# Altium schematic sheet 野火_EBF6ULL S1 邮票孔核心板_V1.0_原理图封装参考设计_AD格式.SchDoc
size 431 x 279 mm
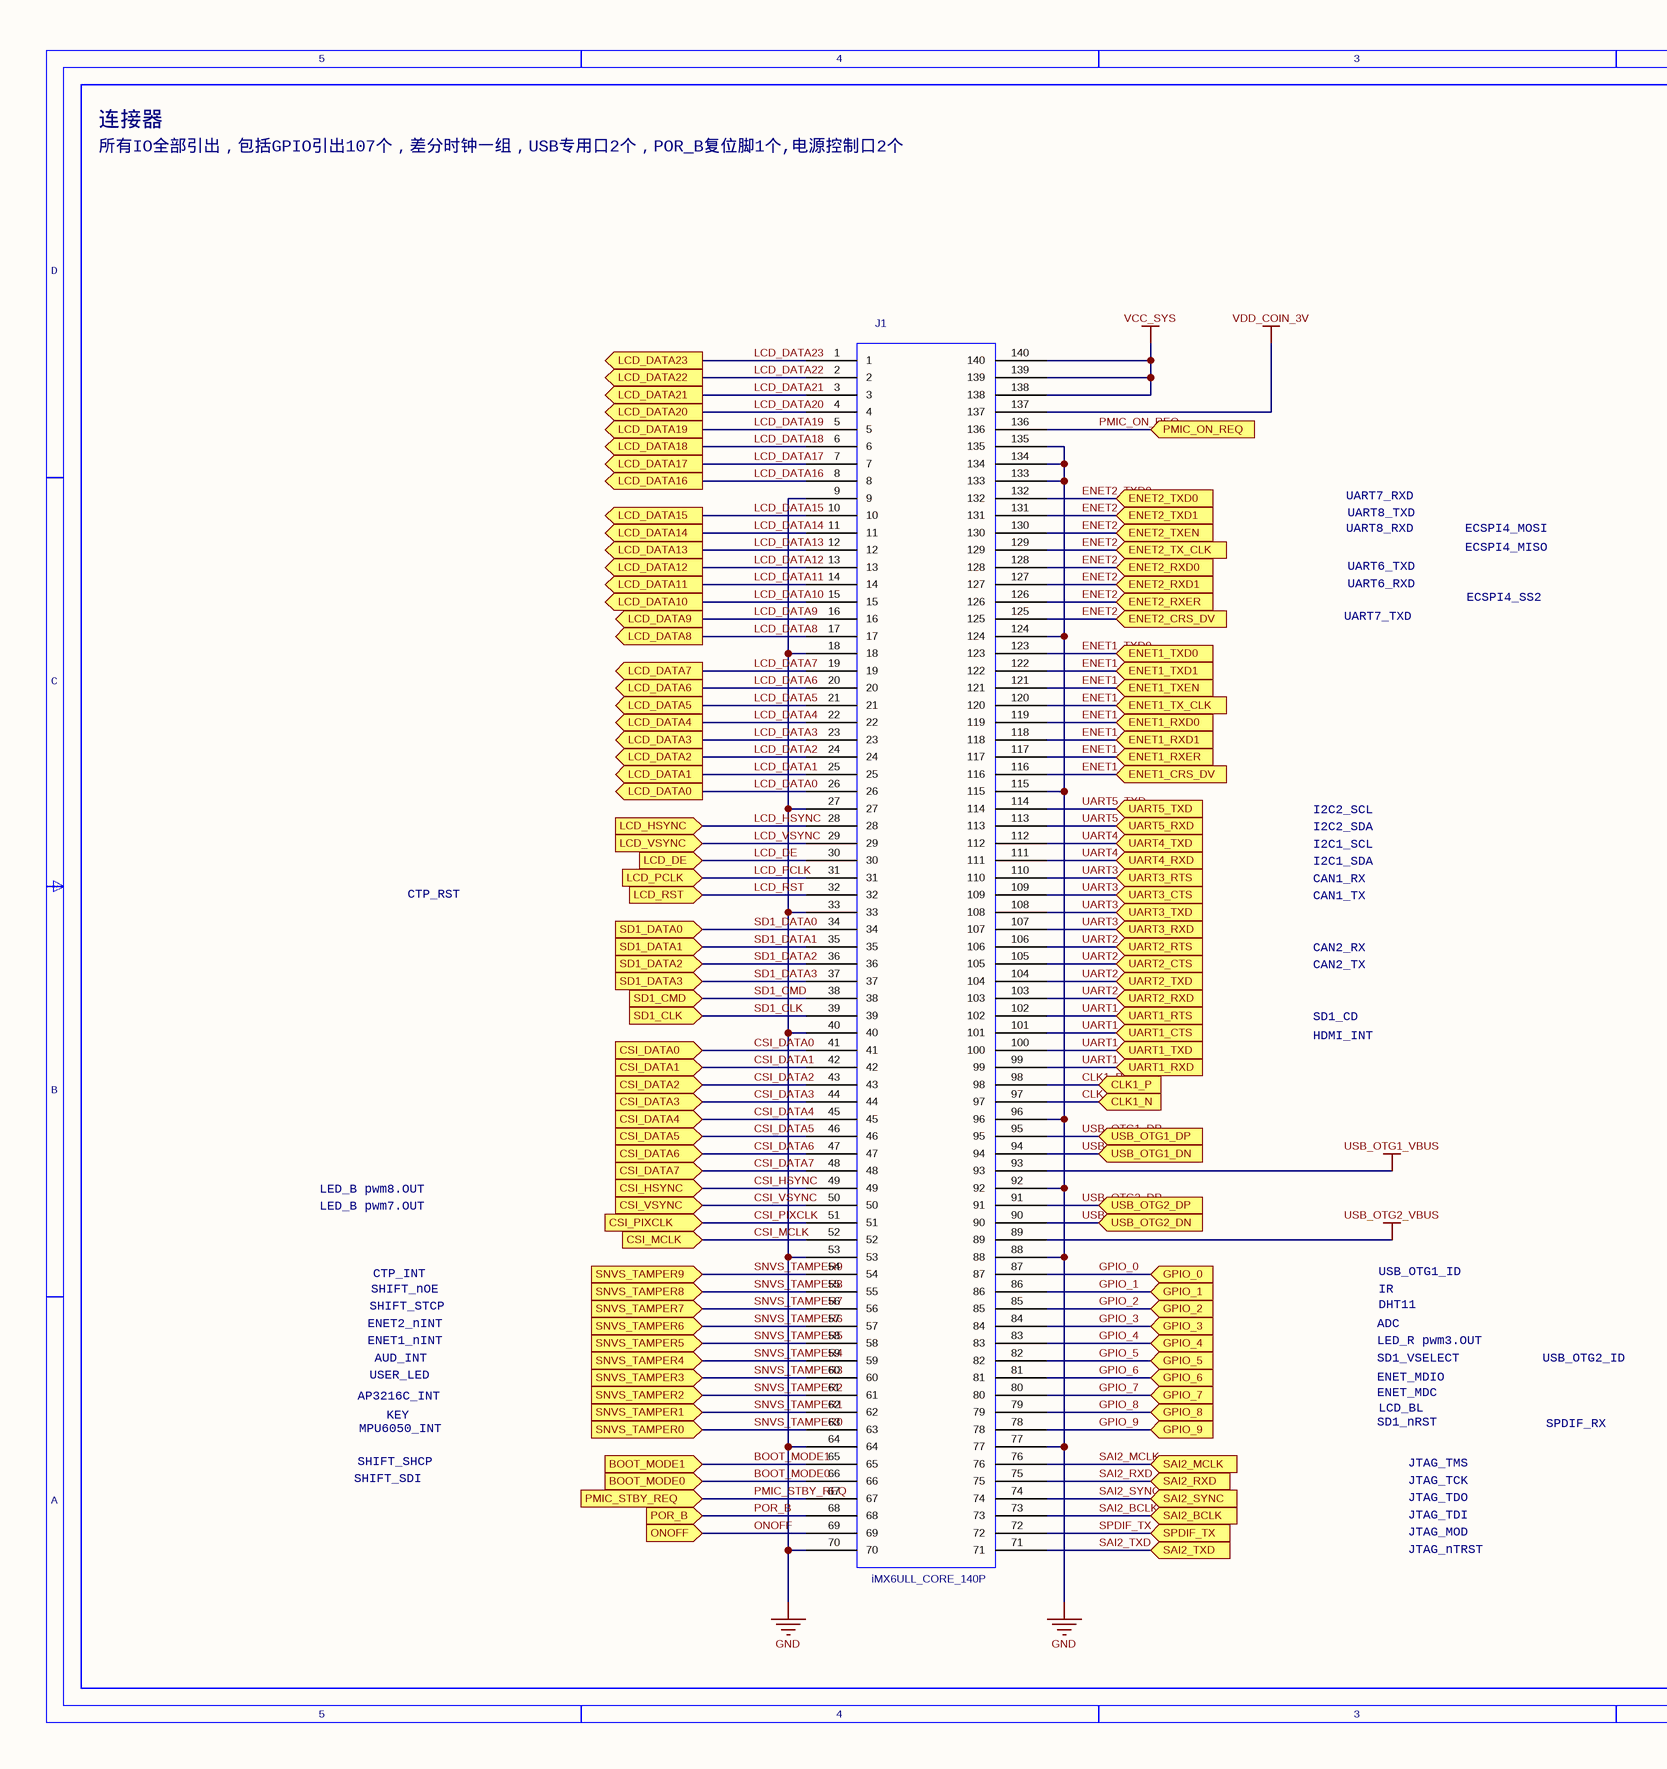
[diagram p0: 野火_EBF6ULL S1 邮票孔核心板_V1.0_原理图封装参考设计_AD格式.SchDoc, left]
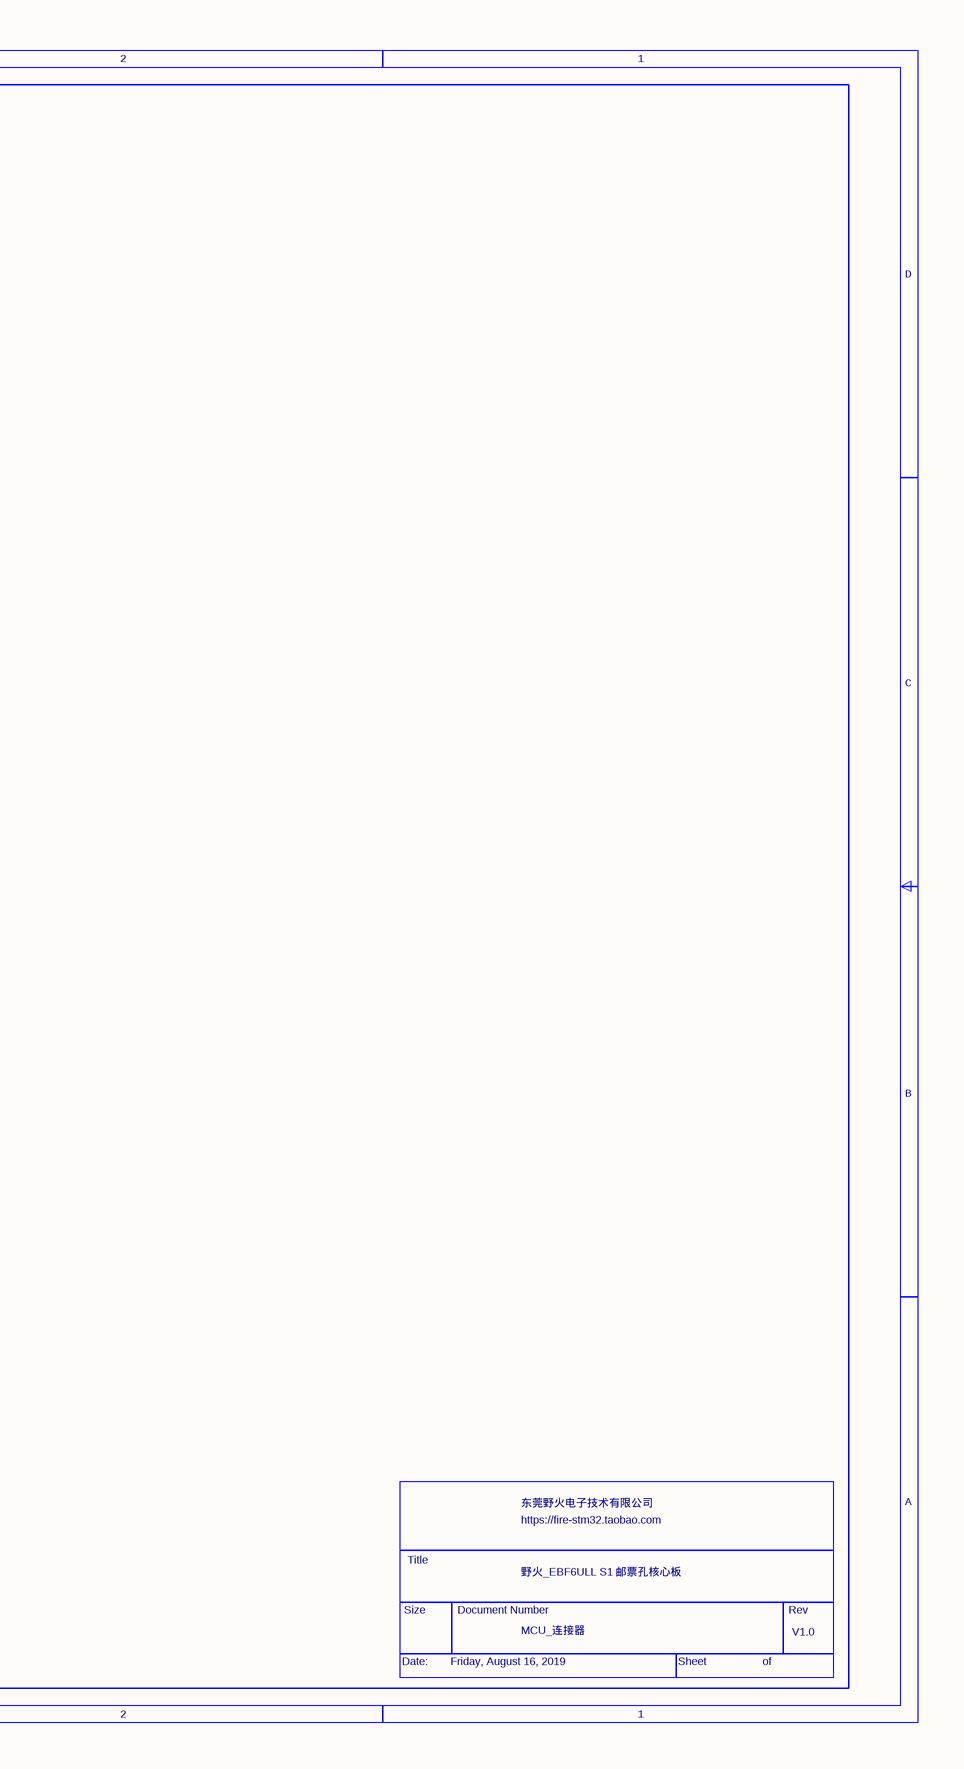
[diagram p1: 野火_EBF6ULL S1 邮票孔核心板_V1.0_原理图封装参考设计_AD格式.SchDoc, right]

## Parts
J1  IMX6ULL_CORE_140P  [6ULL_CORE_140P_39X39]

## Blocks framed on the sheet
连接器: J1

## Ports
BOOT_MODE0, BOOT_MODE1, CLK1_N (in), CLK1_P (in), CSI_DATA0, CSI_DATA1, CSI_DATA2, CSI_DATA3, CSI_DATA4, CSI_DATA5, CSI_DATA6, CSI_DATA7, CSI_HSYNC, CSI_MCLK, CSI_PIXCLK, CSI_VSYNC, ENET1_CRS_DV (in), ENET1_RXD0 (in), ENET1_RXD1 (in), ENET1_RXER (in), ENET1_TX_CLK (in), ENET1_TXD0 (in), ENET1_TXD1 (in), ENET1_TXEN (in), ENET2_CRS_DV (in), ENET2_RXD0 (in), ENET2_RXD1 (in), ENET2_RXER (in), ENET2_TX_CLK (in), ENET2_TXD0 (in), ENET2_TXD1 (in), ENET2_TXEN (in), GPIO_0 (in), GPIO_1 (in), GPIO_2 (in), GPIO_3 (in), GPIO_4 (in), GPIO_5 (in), GPIO_6 (in), GPIO_7 (in), GPIO_8 (in), GPIO_9 (in), LCD_DATA0 (out), LCD_DATA1 (out), LCD_DATA2 (out), LCD_DATA3 (out), LCD_DATA4 (out), LCD_DATA5 (out), LCD_DATA6 (out), LCD_DATA7 (out), LCD_DATA8 (out), LCD_DATA9 (out), LCD_DATA10 (out), LCD_DATA11 (out), LCD_DATA12 (out), LCD_DATA13 (out), LCD_DATA14 (out), LCD_DATA15 (out), LCD_DATA16 (out), LCD_DATA17 (out), LCD_DATA18 (out), LCD_DATA19 (out), LCD_DATA20 (out), LCD_DATA21 (out), LCD_DATA22 (out), LCD_DATA23 (out), LCD_DE, LCD_HSYNC, LCD_PCLK, LCD_RST, LCD_VSYNC, ONOFF, PMIC_ON_REQ, PMIC_STBY_REQ, POR_B, SAI2_BCLK (in), SAI2_MCLK (in), SAI2_RXD (in), SAI2_SYNC (in), SAI2_TXD (in), SD1_CLK, SD1_CMD, SD1_DATA0, SD1_DATA1, SD1_DATA2, SD1_DATA3, SNVS_TAMPER0, SNVS_TAMPER1, SNVS_TAMPER2, SNVS_TAMPER3, SNVS_TAMPER4, SNVS_TAMPER5, SNVS_TAMPER6, SNVS_TAMPER7, SNVS_TAMPER8, SNVS_TAMPER9, SPDIF_TX (in), UART1_CTS, UART1_RTS, UART1_RXD, UART1_TXD, UART2_CTS, UART2_RTS, UART2_RXD, UART2_TXD, UART3_CTS, UART3_RTS, UART3_RXD, UART3_TXD, UART4_RXD, UART4_TXD, UART5_RXD, UART5_TXD, USB_OTG1_DN (in), USB_OTG1_DP (in), USB_OTG2_DN (in), USB_OTG2_DP (in)

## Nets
GND: J1.9 J1.18 J1.27 J1.33 J1.40 J1.53 J1.64 J1.70 J1.77 J1.88 J1.92 J1.96 J1.115 J1.124 J1.133 J1.134 J1.135
USB_OTG1_VBUS: J1.93
USB_OTG2_VBUS: J1.89
VCC_SYS: J1.138 J1.139 J1.140
VDD_COIN_3V: J1.137
BOOT_MODE0: J1.66 ; port BOOT_MODE0
BOOT_MODE1: J1.65 ; port BOOT_MODE1
CLK1_N: J1.97 ; port CLK1_N
CLK1_P: J1.98 ; port CLK1_P
CSI_DATA0: J1.41 ; port CSI_DATA0
CSI_DATA1: J1.42 ; port CSI_DATA1
CSI_DATA2: J1.43 ; port CSI_DATA2
CSI_DATA3: J1.44 ; port CSI_DATA3
CSI_DATA4: J1.45 ; port CSI_DATA4
CSI_DATA5: J1.46 ; port CSI_DATA5
CSI_DATA6: J1.47 ; port CSI_DATA6
CSI_DATA7: J1.48 ; port CSI_DATA7
CSI_HSYNC: J1.49 ; port CSI_HSYNC
CSI_MCLK: J1.52 ; port CSI_MCLK
CSI_PIXCLK: J1.51 ; port CSI_PIXCLK
CSI_VSYNC: J1.50 ; port CSI_VSYNC
ENET1_CRS_DV: J1.116 ; port ENET1_CRS_DV
ENET1_RXD0: J1.119 ; port ENET1_RXD0
ENET1_RXD1: J1.118 ; port ENET1_RXD1
ENET1_RXER: J1.117 ; port ENET1_RXER
ENET1_TX_CLK: J1.120 ; port ENET1_TX_CLK
ENET1_TXD0: J1.123 ; port ENET1_TXD0
ENET1_TXD1: J1.122 ; port ENET1_TXD1
ENET1_TXEN: J1.121 ; port ENET1_TXEN
ENET2_CRS_DV: J1.125 ; port ENET2_CRS_DV
ENET2_RXD0: J1.128 ; port ENET2_RXD0
ENET2_RXD1: J1.127 ; port ENET2_RXD1
ENET2_RXER: J1.126 ; port ENET2_RXER
ENET2_TX_CLK: J1.129 ; port ENET2_TX_CLK
ENET2_TXD0: J1.132 ; port ENET2_TXD0
ENET2_TXD1: J1.131 ; port ENET2_TXD1
ENET2_TXEN: J1.130 ; port ENET2_TXEN
GPIO_0: J1.87 ; port GPIO_0
GPIO_1: J1.86 ; port GPIO_1
GPIO_2: J1.85 ; port GPIO_2
GPIO_3: J1.84 ; port GPIO_3
GPIO_4: J1.83 ; port GPIO_4
GPIO_5: J1.82 ; port GPIO_5
GPIO_6: J1.81 ; port GPIO_6
GPIO_7: J1.80 ; port GPIO_7
GPIO_8: J1.79 ; port GPIO_8
GPIO_9: J1.78 ; port GPIO_9
LCD_DATA0: J1.26 ; port LCD_DATA0
LCD_DATA1: J1.25 ; port LCD_DATA1
LCD_DATA2: J1.24 ; port LCD_DATA2
LCD_DATA3: J1.23 ; port LCD_DATA3
LCD_DATA4: J1.22 ; port LCD_DATA4
LCD_DATA5: J1.21 ; port LCD_DATA5
LCD_DATA6: J1.20 ; port LCD_DATA6
LCD_DATA7: J1.19 ; port LCD_DATA7
LCD_DATA8: J1.17 ; port LCD_DATA8
LCD_DATA9: J1.16 ; port LCD_DATA9
LCD_DATA10: J1.15 ; port LCD_DATA10
LCD_DATA11: J1.14 ; port LCD_DATA11
LCD_DATA12: J1.13 ; port LCD_DATA12
LCD_DATA13: J1.12 ; port LCD_DATA13
LCD_DATA14: J1.11 ; port LCD_DATA14
LCD_DATA15: J1.10 ; port LCD_DATA15
LCD_DATA16: J1.8 ; port LCD_DATA16
LCD_DATA17: J1.7 ; port LCD_DATA17
LCD_DATA18: J1.6 ; port LCD_DATA18
LCD_DATA19: J1.5 ; port LCD_DATA19
LCD_DATA20: J1.4 ; port LCD_DATA20
LCD_DATA21: J1.3 ; port LCD_DATA21
LCD_DATA22: J1.2 ; port LCD_DATA22
LCD_DATA23: J1.1 ; port LCD_DATA23
LCD_DE: J1.30 ; port LCD_DE
LCD_HSYNC: J1.28 ; port LCD_HSYNC
LCD_PCLK: J1.31 ; port LCD_PCLK
LCD_RST: J1.32 ; port LCD_RST
LCD_VSYNC: J1.29 ; port LCD_VSYNC
ONOFF: J1.69 ; port ONOFF
PMIC_ON_REQ: J1.136 ; port PMIC_ON_REQ
PMIC_STBY_REQ: J1.67 ; port PMIC_STBY_REQ
POR_B: J1.68 ; port POR_B
SAI2_BCLK: J1.73 ; port SAI2_BCLK
SAI2_MCLK: J1.76 ; port SAI2_MCLK
SAI2_RXD: J1.75 ; port SAI2_RXD
SAI2_SYNC: J1.74 ; port SAI2_SYNC
SAI2_TXD: J1.71 ; port SAI2_TXD
SD1_CLK: J1.39 ; port SD1_CLK
SD1_CMD: J1.38 ; port SD1_CMD
SD1_DATA0: J1.34 ; port SD1_DATA0
SD1_DATA1: J1.35 ; port SD1_DATA1
SD1_DATA2: J1.36 ; port SD1_DATA2
SD1_DATA3: J1.37 ; port SD1_DATA3
SNVS_TAMPER0: J1.63 ; port SNVS_TAMPER0
SNVS_TAMPER1: J1.62 ; port SNVS_TAMPER1
SNVS_TAMPER2: J1.61 ; port SNVS_TAMPER2
SNVS_TAMPER3: J1.60 ; port SNVS_TAMPER3
SNVS_TAMPER4: J1.59 ; port SNVS_TAMPER4
SNVS_TAMPER5: J1.58 ; port SNVS_TAMPER5
SNVS_TAMPER6: J1.57 ; port SNVS_TAMPER6
SNVS_TAMPER7: J1.56 ; port SNVS_TAMPER7
SNVS_TAMPER8: J1.55 ; port SNVS_TAMPER8
SNVS_TAMPER9: J1.54 ; port SNVS_TAMPER9
SPDIF_TX: J1.72 ; port SPDIF_TX
UART1_CTS: J1.101 ; port UART1_CTS
UART1_RTS: J1.102 ; port UART1_RTS
UART1_RXD: J1.99 ; port UART1_RXD
UART1_TXD: J1.100 ; port UART1_TXD
UART2_CTS: J1.105 ; port UART2_CTS
UART2_RTS: J1.106 ; port UART2_RTS
UART2_RXD: J1.103 ; port UART2_RXD
UART2_TXD: J1.104 ; port UART2_TXD
UART3_CTS: J1.109 ; port UART3_CTS
UART3_RTS: J1.110 ; port UART3_RTS
UART3_RXD: J1.107 ; port UART3_RXD
UART3_TXD: J1.108 ; port UART3_TXD
UART4_RXD: J1.111 ; port UART4_RXD
UART4_TXD: J1.112 ; port UART4_TXD
UART5_RXD: J1.113 ; port UART5_RXD
UART5_TXD: J1.114 ; port UART5_TXD
USB_OTG1_DN: J1.94 ; port USB_OTG1_DN
USB_OTG1_DP: J1.95 ; port USB_OTG1_DP
USB_OTG2_DN: J1.90 ; port USB_OTG2_DN
USB_OTG2_DP: J1.91 ; port USB_OTG2_DP

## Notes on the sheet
- 5
- 4
- 3
- 2
- 1
- 所有IO全部引出，包括GPIO引出107个，差分时钟一组，USB专用口2个，POR_B复位脚1个,电源控制口2个
- D
- UART7_RXD
- UART8_RXD
- UART6_TXD
- UART6_RXD
- UART8_TXD
- ECSPI4_MOSI
- ECSPI4_MISO
- C
- UART7_TXD
- ECSPI4_SS2
- I2C2_SDA
- I2C1_SCL
- I2C2_SCL
- CTP_RST
- I2C1_SDA
- CAN1_TX
- CAN1_RX
- CAN2_TX
- CAN2_RX
- SD1_CD
- B
- HDMI_INT
- LED_B pwm8.OUT
- LED_B pwm7.OUT
- CTP_INT
- USB_OTG1_ID
- ENET2_nINT
- ENET1_nINT
- SHIFT_STCP
- SHIFT_nOE
- AUD_INT
- ADC
- LED_R pwm3.OUT
- SD1_VSELECT
- IR
- DHT11
- USB_OTG2_ID
- AP3216C_INT
- MPU6050_INT
- USER_LED
- KEY
- ENET_MDIO
- ENET_MDC
- SD1_nRST
- LCD_BL
- SPDIF_RX
- A
- SHIFT_SDI
- SHIFT_SHCP
- JTAG_TCK
- JTAG_TDI
- JTAG_MOD
- JTAG_TDO
- JTAG_TMS
- https://fire-stm32.taobao.com
- 东莞野火电子技术有限公司
- JTAG_nTRST
- Size
- Title
- Document Number
- 野火_EBF6ULL S1 邮票孔核心板
- Rev
- Date:
- Friday, August 16, 2019
- MCU_连接器
- Sheet
- of
- V1.0

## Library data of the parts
J1 = IMX6ULL_CORE_140P: Source_Path: C:\MYPROGRAM\CADENCE\SPB_16.6\TOOLS\CAPTURE\LIBRARY\SCH.OLB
